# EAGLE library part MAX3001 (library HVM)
MAXIM 8-CH BI-DIRECTIONAL LEVEL TRANSLATOR
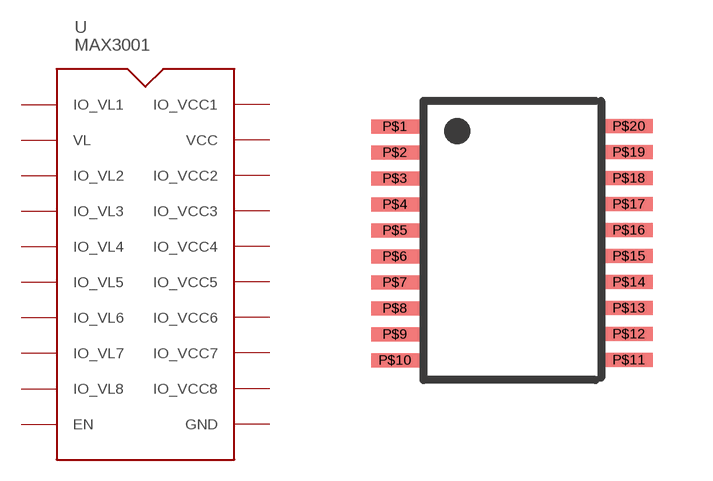
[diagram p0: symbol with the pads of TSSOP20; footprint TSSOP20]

Designator prefix U

## MAX3001  [TSSOP20]
P$1  IO_VL1  pas
P$2  VL  pas
P$3  IO_VL2  pas
P$4  IO_VL3  pas
P$5  IO_VL4  pas
P$6  IO_VL5  pas
P$7  IO_VL6  pas
P$8  IO_VL7  pas
P$9  IO_VL8  pas
P$10  EN  pas
P$11  GND  pas
P$12  IO_VCC8  pas
P$13  IO_VCC7  pas
P$14  IO_VCC6  pas
P$15  IO_VCC5  pas
P$16  IO_VCC4  pas
P$17  IO_VCC3  pas
P$18  IO_VCC2  pas
P$19  VCC  pas
P$20  IO_VCC1  pas

## Footprint TSSOP20 (pad centres in mm)
TSSOP20 CREATED BY NK USING TSSOP8 DATA
smd 1.2 x 0.35: P$1 0,5.842; P$2 0,5.192; P$3 0,4.542; P$4 0,3.892; P$5 0,3.242; P$6 0,2.592; P$7 0,1.942; P$8 0,1.292; P$9 0,0.642; P$10 0,-0.008; P$11 5.85,0; P$12 5.85,0.65; P$13 5.85,1.3; P$14 5.85,1.95; P$15 5.85,2.6; P$16 5.85,3.25; P$17 5.85,3.9; P$18 5.85,4.55; P$19 5.85,5.2; P$20 5.85,5.85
